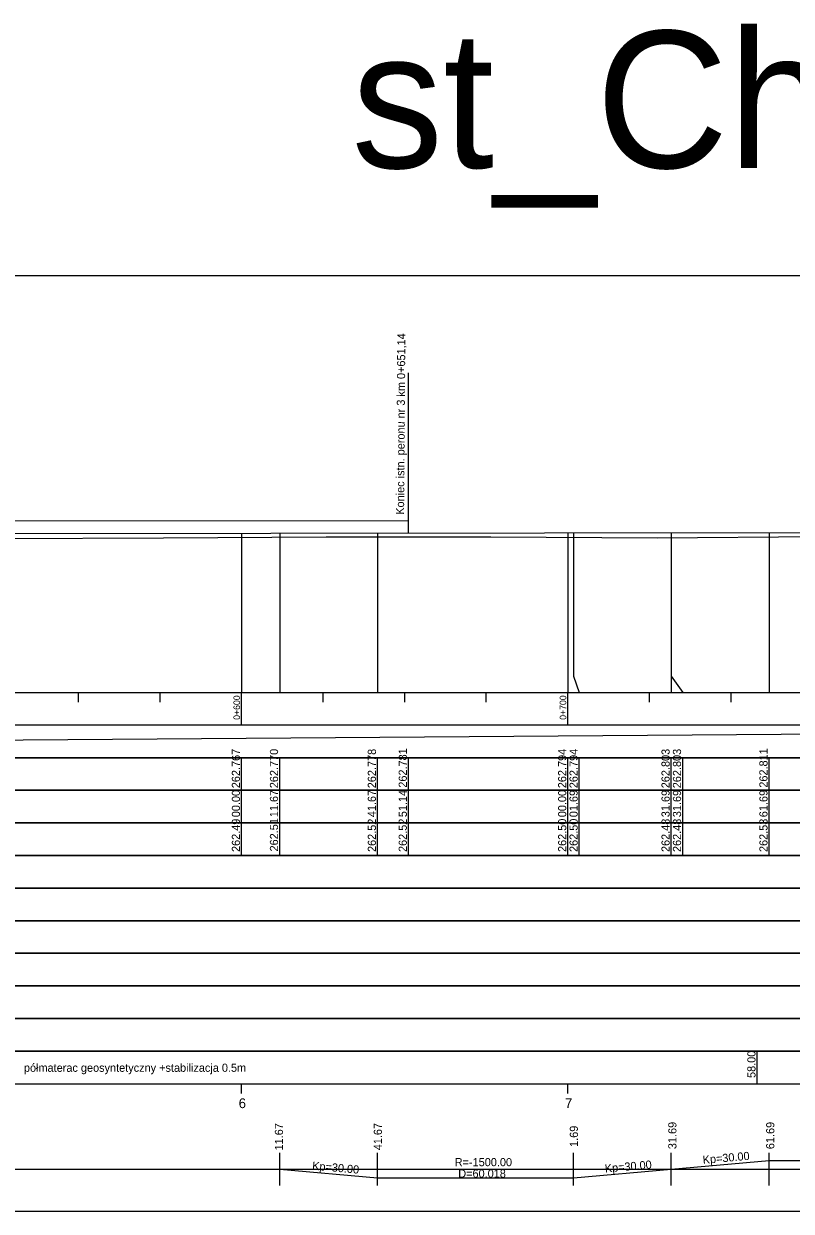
# Model space of a CAD drawing. Extents: x 6445630 to 6518227, y 5499240 to 5511716.
# Drawn here: x 6452864.4 to 6453099.7, y 5504866.4 to 5505230.7 of the extents above; entities that cross this region are included whole.
import ezdxf

# ---------------------------------------------------------------- set-up
doc = ezdxf.new("R2010")
doc.units = 0
for name, color, linetype in [('TOR_PROF-obiekty+opisy', 7, 'Continuous'), ('TOR_PROF-opisy pomocnicze', 7, 'Continuous'), ('TOR_PROF-tabelka-geometria T1', 7, 'Continuous'), ('TOR_PROF-tabelka-kilometracja', 7, 'Continuous'), ('TOR_PROF-tabelka-odleglosci T1', 7, 'Continuous'), ('TOR_PROF-tabelka-pochylenia proj T1', 7, 'Continuous'), ('TOR_PROF-tabelka-rodzaj rowu T1', 7, 'Continuous'), ('TOR_PROF-tabelka-rowyT1', 7, 'Continuous'), ('TOR_PROF-tabelka-rurociagi T1', 7, 'Continuous'), ('TOR_PROF-tabelka-rzedne istn T1', 7, 'Continuous'), ('TOR_PROF-tabelka-rzedne proj T1', 7, 'Continuous'), ('TOR_PROF-tabelka-teren istniejacy T1', 7, 'Continuous'), ('TOR_PROF-tabelka-warstwa ochronna T1', 7, 'Continuous'), ('TOR_PROF-tor istniejacy T1', 7, 'Continuous'), ('TOR_PROF-tor projektowany', 7, 'Continuous'), ('TOR_PROF-uklad odniesienia', 7, 'Continuous'), ('TOR_PROF-warstwa ochronna', 7, 'Continuous'), ('TOR_RAMKI-MASKA WYCIECIA', 7, 'Continuous')]:
    doc.layers.add(name, color=color, linetype=linetype)

msp = doc.modelspace()

# ---------------------------------------------------------------- linework, layer by layer
at = {"layer": 'TOR_PROF-obiekty+opisy'}
for p, q in [((6452982.35, 5505078.21), (6452982.35, 5505123.63)), ((6452982.35, 5505078.27), (6452681.97, 5505077.87)), ((6452982.35, 5505074.47), (6452982.35, 5505078.27))]:
    msp.add_line(p, q, dxfattribs=at)
at = {"layer": 'TOR_PROF-tabelka-geometria T1'}
for points in [[(6452942.88, 5504874.34), (6452942.88, 5504884.34)], [(6452972.88, 5504874.34), (6452972.88, 5504884.34)], [(6453032.9, 5504874.34), (6453032.9, 5504884.34)], [(6453062.9, 5504874.34), (6453062.9, 5504884.34)], [(6453062.9, 5504874.34), (6453062.9, 5504884.34)], [(6453092.9, 5504874.34), (6453092.9, 5504884.34)], [(6452609.55, 5504876.67), (6452697.82, 5504876.67), (6452697.82, 5504879.34), (6452942.88, 5504879.34), (6452942.88, 5504879.34), (6452972.88, 5504876.67), (6452972.88, 5504876.67), (6453032.9, 5504876.67), (6453032.9, 5504876.67), (6453062.9, 5504879.34), (6453062.9, 5504879.34), (6453062.9, 5504879.34), (6453062.9, 5504879.34), (6453092.9, 5504882), (6453092.9, 5504882), (6453152.92, 5504882), (6453152.92, 5504882), (6453182.92, 5504879.34), (6453182.92, 5504879.34), (6454010.63, 5504879.34)], [(6452331.21, 5504879.34), (6454031.21, 5504879.34)]]:
    msp.add_lwpolyline(points, dxfattribs=at)
at = {"layer": 'TOR_PROF-tabelka-kilometracja'}
msp.add_line((6453089.21, 5504905.57), (6453089.21, 5504915.57), dxfattribs=at)
for points in [[(6452931.21, 5504902.57), (6452931.21, 5504905.57)], [(6453031.21, 5504902.57), (6453031.21, 5504905.57)]]:
    msp.add_lwpolyline(points, dxfattribs=at)
at = {"layer": 'TOR_PROF-tabelka-odleglosci T1'}
msp.add_lwpolyline([(6452331.21, 5504985.57), (6454031.21, 5504985.57), (6454031.21, 5504995.57), (6452331.21, 5504995.57)], close=True, dxfattribs=at)
for points in [[(6452931.21, 5504985.57), (6452931.21, 5504995.57)], [(6452942.88, 5504985.57), (6452942.88, 5504995.57)], [(6452972.88, 5504985.57), (6452972.88, 5504995.57)], [(6452982.35, 5504985.57), (6452982.35, 5504995.57)], [(6453031.21, 5504985.57), (6453031.21, 5504995.57)], [(6453034.71, 5504985.57), (6453034.71, 5504995.57)], [(6453062.9, 5504985.57), (6453062.9, 5504995.57)], [(6453066.4, 5504985.57), (6453066.4, 5504995.57)], [(6453092.9, 5504985.57), (6453092.9, 5504995.57)]]:
    msp.add_lwpolyline(points, dxfattribs=at)
at = {"layer": 'TOR_PROF-tabelka-pochylenia proj T1'}
msp.add_lwpolyline([(6452331.21, 5505005.57), (6454031.21, 5505005.57), (6454031.21, 5505015.57), (6452331.21, 5505015.57)], close=True, dxfattribs=at)
msp.add_lwpolyline([(6452331.21, 5505007.07), (6453274.21, 5505014.07)], dxfattribs=at)
at = {"layer": 'TOR_PROF-tabelka-rodzaj rowu T1'}
for points in [[(6452331.21, 5504945.57), (6454031.21, 5504945.57), (6454031.21, 5504955.57), (6452331.21, 5504955.57)], [(6452331.21, 5504925.57), (6454031.21, 5504925.57), (6454031.21, 5504935.57), (6452331.21, 5504935.57)]]:
    msp.add_lwpolyline(points, close=True, dxfattribs=at)
at = {"layer": 'TOR_PROF-tabelka-rowyT1'}
msp.add_lwpolyline([(6452331.21, 5504955.57), (6454031.21, 5504955.57), (6454031.21, 5504965.57), (6452331.21, 5504965.57)], close=True, dxfattribs=at)
at = {"layer": 'TOR_PROF-tabelka-rurociagi T1'}
msp.add_lwpolyline([(6452331.21, 5504935.57), (6454031.21, 5504935.57), (6454031.21, 5504945.57), (6452331.21, 5504945.57)], close=True, dxfattribs=at)
at = {"layer": 'TOR_PROF-tabelka-rzedne istn T1'}
msp.add_lwpolyline([(6452331.21, 5504975.57), (6454031.21, 5504975.57), (6454031.21, 5504985.57), (6452331.21, 5504985.57)], close=True, dxfattribs=at)
for points in [[(6452931.21, 5504975.57), (6452931.21, 5504985.57)], [(6452942.88, 5504975.57), (6452942.88, 5504985.57)], [(6452972.88, 5504975.57), (6452972.88, 5504985.57)], [(6452982.35, 5504975.57), (6452982.35, 5504985.57)], [(6453031.21, 5504975.57), (6453031.21, 5504985.57)], [(6453034.71, 5504975.57), (6453034.71, 5504985.57)], [(6453062.9, 5504975.57), (6453062.9, 5504985.57)], [(6453066.4, 5504975.57), (6453066.4, 5504985.57)], [(6453092.9, 5504975.57), (6453092.9, 5504985.57)]]:
    msp.add_lwpolyline(points, dxfattribs=at)
at = {"layer": 'TOR_PROF-tabelka-rzedne proj T1'}
msp.add_lwpolyline([(6452331.21, 5504995.57), (6454031.21, 5504995.57), (6454031.21, 5505005.57), (6452331.21, 5505005.57)], close=True, dxfattribs=at)
for points in [[(6452931.21, 5504995.57), (6452931.21, 5505005.57)], [(6452942.88, 5504995.57), (6452942.88, 5505005.57)], [(6452972.88, 5504995.57), (6452972.88, 5505005.57)], [(6452982.35, 5504995.57), (6452982.35, 5505005.57)], [(6453031.21, 5504995.57), (6453031.21, 5505005.57)], [(6453034.71, 5504995.57), (6453034.71, 5505005.57)], [(6453062.9, 5504995.57), (6453062.9, 5505005.57)], [(6453066.4, 5504995.57), (6453066.4, 5505005.57)], [(6453092.9, 5504995.57), (6453092.9, 5505005.57)]]:
    msp.add_lwpolyline(points, dxfattribs=at)
at = {"layer": 'TOR_PROF-tabelka-teren istniejacy T1'}
msp.add_lwpolyline([(6452331.21, 5504965.57), (6454031.21, 5504965.57), (6454031.21, 5504975.57), (6452331.21, 5504975.57)], close=True, dxfattribs=at)
at = {"layer": 'TOR_PROF-tabelka-warstwa ochronna T1'}
msp.add_lwpolyline([(6452331.21, 5504915.57), (6454031.21, 5504915.57), (6454031.21, 5504925.57), (6452331.21, 5504925.57)], close=True, dxfattribs=at)
at = {"layer": 'TOR_PROF-tor istniejacy T1'}
msp.add_lwpolyline([(6453371.96, 5505074.17), (6453352.39, 5505074.07), (6453302.02, 5505073.67), (6453250.29, 5505073.32), (6453203.56, 5505073.17), (6453158.6, 5505073.42), (6453108.1, 5505073.32), (6453058.53, 5505072.92), (6453007.58, 5505073.17), (6452957.17, 5505073.17), (6452907.31, 5505072.92), (6452857.67, 5505072.72), (6452808.05, 5505072.87), (6452758.83, 5505072.77), (6452706.3, 5505072.77), (6452657.09, 5505073.22)], dxfattribs=at)
at = {"layer": 'TOR_PROF-tor projektowany'}
msp.add_line((6452331.21, 5505073.6), (6453274.21, 5505074.87), dxfattribs=at)
for points in [[(6452931.21, 5505074.41), (6452931.21, 5505030.57), (6452931.21, 5505025.57), (6452931.21, 5505025.57)], [(6452931.21, 5505074.41), (6452931.21, 5505030.57), (6452931.21, 5505025.57), (6452931.21, 5505025.57)], [(6452942.88, 5505074.42), (6452942.88, 5505030.57), (6452942.88, 5505025.57), (6452942.88, 5505025.57)], [(6452942.88, 5505074.42), (6452942.88, 5505030.57), (6452942.88, 5505025.57), (6452942.88, 5505025.57)], [(6452972.88, 5505074.46), (6452972.88, 5505030.57), (6452972.88, 5505025.57), (6452972.88, 5505025.57)], [(6452972.88, 5505074.46), (6452972.88, 5505030.57), (6452972.88, 5505025.57), (6452972.88, 5505025.57)], [(6453031.21, 5505074.54), (6453031.21, 5505030.57), (6453031.21, 5505025.57), (6453031.21, 5505025.57)], [(6453031.21, 5505074.54), (6453031.21, 5505030.57), (6453031.21, 5505025.57), (6453031.21, 5505025.57)], [(6453032.9, 5505074.54), (6453032.9, 5505030.57), (6453034.71, 5505025.57), (6453034.71, 5505025.57)], [(6453032.9, 5505074.54), (6453032.9, 5505030.57), (6453034.71, 5505025.57), (6453034.71, 5505025.57)], [(6453062.9, 5505074.58), (6453062.9, 5505030.57), (6453062.9, 5505025.57), (6453062.9, 5505025.57)], [(6453062.9, 5505074.58), (6453062.9, 5505030.57), (6453066.4, 5505025.57), (6453066.4, 5505025.57)], [(6453062.9, 5505074.58), (6453062.9, 5505030.57), (6453062.9, 5505025.57), (6453062.9, 5505025.57)], [(6453062.9, 5505074.58), (6453062.9, 5505030.57), (6453066.4, 5505025.57), (6453066.4, 5505025.57)], [(6453092.9, 5505074.62), (6453092.9, 5505030.57), (6453092.9, 5505025.57), (6453092.9, 5505025.57)], [(6453092.9, 5505074.62), (6453092.9, 5505030.57), (6453092.9, 5505025.57), (6453092.9, 5505025.57)]]:
    msp.add_lwpolyline(points, dxfattribs=at)
at = {"layer": 'TOR_PROF-uklad odniesienia'}
for p, q in [((6452331.21, 5505025.57), (6454031.21, 5505025.57)), ((6452881.21, 5505022.57), (6452881.21, 5505025.57)), ((6452906.21, 5505022.57), (6452906.21, 5505025.57)), ((6452931.21, 5505015.57), (6452931.21, 5505025.57)), ((6452956.21, 5505022.57), (6452956.21, 5505025.57)), ((6452981.21, 5505022.57), (6452981.21, 5505025.57)), ((6453006.21, 5505022.57), (6453006.21, 5505025.57)), ((6453031.21, 5505015.57), (6453031.21, 5505025.57)), ((6453056.21, 5505022.57), (6453056.21, 5505025.57)), ((6453081.21, 5505022.57), (6453081.21, 5505025.57))]:
    msp.add_line(p, q, dxfattribs=at)
at = {"layer": 'TOR_PROF-warstwa ochronna'}
msp.add_lwpolyline([(6452331.21, 5504905.57), (6454031.21, 5504905.57), (6454031.21, 5504915.57), (6452331.21, 5504915.57)], close=True, dxfattribs=at)
at = {"layer": 'TOR_RAMKI-MASKA WYCIECIA'}
msp.add_lwpolyline([(6452265.88, 5504866.43), (6454055.88, 5504866.43), (6454055.88, 5505153.43), (6452265.88, 5505153.43)], close=True, dxfattribs=at)

# ---------------------------------------------------------------- texts
at = {"layer": 'TOR_PROF-obiekty+opisy'}
msp.add_text('Koniec istn. peronu nr 3 km 0+651,14', height=2.5, rotation=89.574, dxfattribs=at).set_placement((6452981, 5505080.1))
at = {"layer": 'TOR_PROF-opisy pomocnicze'}
for s, p in [('11.67', (6452943.9, 5504885.08)), ('41.67', (6452974.22, 5504885.14)), ('1.69', (6453034.29, 5504886.17))]:
    msp.add_text(s, height=2.5, rotation=90, dxfattribs=at).set_placement(p)
at = {"layer": 'TOR_PROF-tabelka-geometria T1'}
for rotation, p in [(5.0796, (6453072.64, 5504880.95)), (354.9204, (6452952.76, 5504879.21)), (5.0796, (6453042.64, 5504878.29))]:
    msp.add_text('Kp=30.00', height=2.5, rotation=rotation, dxfattribs=at).set_placement(p)
for s, p in [('R=-1500.00', (6452996.53, 5504880.25)), ('D=60.018', (6452997.61, 5504876.75))]:
    msp.add_text(s, height=2.5, dxfattribs=at).set_placement(p)
at = {"layer": 'TOR_PROF-tabelka-kilometracja'}
for s, p in [('6', (6452930.32, 5504898.07)), ('7', (6453030.32, 5504898.07))]:
    msp.add_text(s, height=3, dxfattribs=at).set_placement(p)
at = {"layer": 'TOR_PROF-tabelka-odleglosci T1'}
for s, p in [('00.00', (6452930.71, 5504987.31)), ('11.67', (6452942.38, 5504987.31)), ('41.67', (6452972.38, 5504987.31)), ('51.14', (6452981.85, 5504987.32)), ('00.00', (6453030.71, 5504987.31)), ('01.69', (6453034.21, 5504987.31)), ('31.69', (6453062.4, 5504987.31)), ('31.69', (6453065.9, 5504987.31)), ('61.69', (6453092.4, 5504987.31)), ('31.69', (6453064.48, 5504885.48)), ('61.69', (6453094.48, 5504885.48))]:
    msp.add_text(s, height=2.5, rotation=90, dxfattribs=at).set_placement(p)
at = {"layer": 'TOR_PROF-tabelka-rzedne istn T1'}
for s, p in [('262.49', (6452930.71, 5504976.64)), ('262.51', (6452942.38, 5504976.8)), ('262.52', (6452972.38, 5504976.64)), ('262.52', (6452981.85, 5504976.64)), ('262.50', (6453030.71, 5504976.64)), ('262.50', (6453034.21, 5504976.64)), ('262.48', (6453062.4, 5504976.63)), ('262.48', (6453065.9, 5504976.63)), ('262.53', (6453092.4, 5504976.63))]:
    msp.add_text(s, height=2.5, rotation=90, dxfattribs=at).set_placement(p)
at = {"layer": 'TOR_PROF-tabelka-rzedne proj T1'}
for s, p in [('262.781', (6452981.85, 5504996.37)), ('262.794', (6453030.71, 5504996.21)), ('262.794', (6453034.21, 5504996.21)), ('262.811', (6453092.4, 5504996.37)), ('262.767', (6452930.71, 5504996.21)), ('262.770', (6452942.38, 5504996.21)), ('262.778', (6452972.38, 5504996.2)), ('262.803', (6453062.4, 5504996.2)), ('262.803', (6453065.9, 5504996.2))]:
    msp.add_text(s, height=2.5, rotation=90, dxfattribs=at).set_placement(p)
at = {"layer": 'TOR_PROF-uklad odniesienia'}
msp.add_text('st_Chybie_Tor Nr 5', height=42, dxfattribs=at).set_placement((6452964.89, 5505186.48))
for s, p in [('0+600', (6452930.71, 5505017.18)), ('0+700', (6453030.71, 5505017.18))]:
    msp.add_text(s, height=2, rotation=90, dxfattribs=at).set_placement(p)
at = {"layer": 'TOR_PROF-warstwa ochronna'}
msp.add_text('58.00', height=2.5, rotation=90, dxfattribs=at).set_placement((6453088.71, 5504907.32))
msp.add_text('półmaterac geosyntetyczny +stabilizacja 0.5m', height=2.5, dxfattribs=at).set_placement((6452864.49, 5504909.21))

doc.saveas('drawing.dxf')
